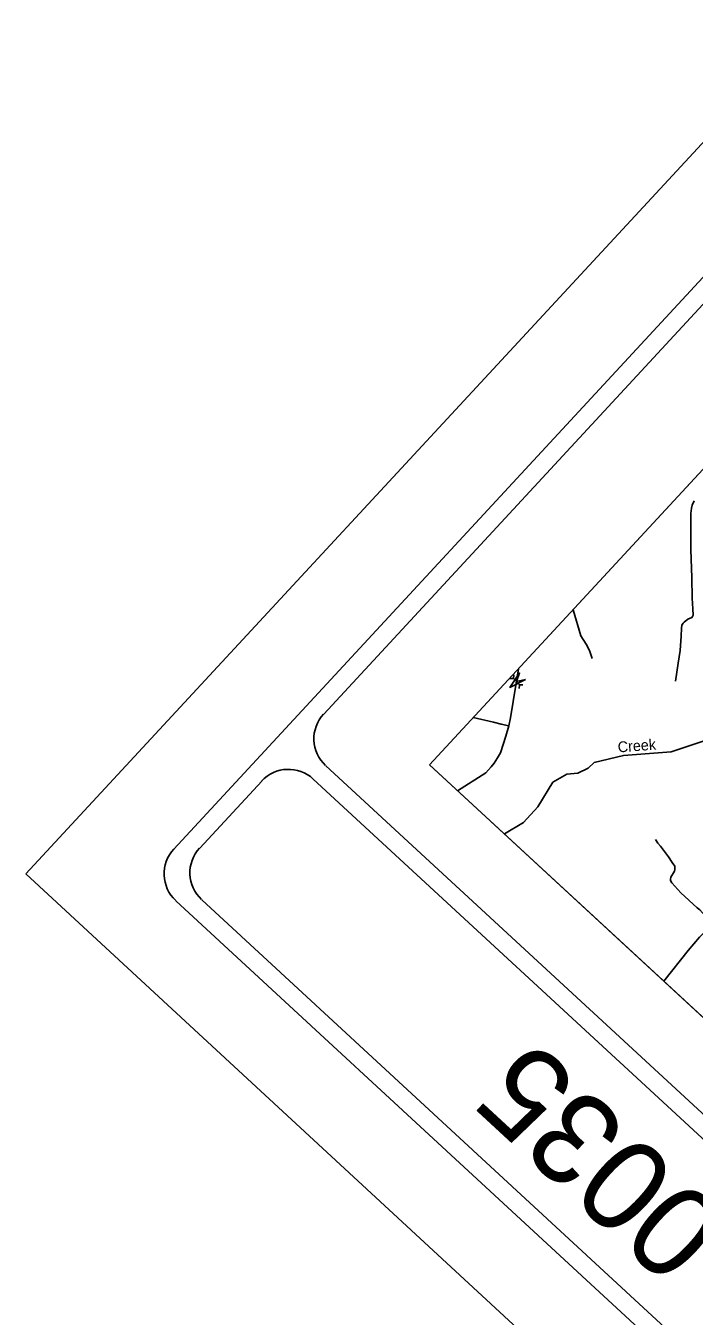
# Model space of a CAD drawing. Extents: x 1766669 to 1770980, y 998119 to 1002502.
# Drawn here: x 1766669 to 1767071, y 999494 to 1000271 of the extents above; entities that cross this region are included whole.
import ezdxf

# ---------------------------------------------------------------- set-up
doc = ezdxf.new("R2010")
doc.units = 0
for name, color, linetype in [('Default', 7, 'Continuous'), ('Default Symbol CELL', 7, 'Continuous'), ('Exist DTM Breakline', 7, 'Continuous'), ('Exist DTM Regular Point CELL', 7, 'Continuous'), ('Exist Property Iron Pin CELL', 7, 'Continuous'), ('Exist Roads EOP', 7, 'Continuous'), ('Exist Utilities Sanitary Sewer Manhole CELL', 7, 'Continuous'), ('PH Exist DTM Breakline', 7, 'Continuous')]:
    doc.layers.add(name, color=color, linetype=linetype)

msp = doc.modelspace()

# ---------------------------------------------------------------- linework, layer by layer
at = {"layer": 'Default'}
msp.add_lwpolyline([(1766911.45, 999825.82), (1767342.39, 1000292.03), (1767769.56, 999897.17), (1767338.62, 999430.96)], close=True, dxfattribs=at)
at = {"layer": 'Default Symbol CELL'}
for p, q in [((1769179.89, 1002395.47), (1766757.68, 999775.07)), ((1769180.49, 1002379.93), (1766847.82, 999856.35)), ((1766911.45, 999825.82), (1767342.36, 1000292.01)), ((1768196.36, 998579.87), (1766849, 999825.3)), ((1767395.61, 999378.28), (1766911.45, 999825.82)), ((1768487.42, 998295.86), (1766841.54, 999817.23))]:
    msp.add_line(p, q, dxfattribs=at)
for points in [[(1766810.51, 999815.99), (1766773.2, 999775.67)], [(1766758.86, 999744.06), (1768420.84, 998207.8)], [(1766758.9, 999744.01), (1768420.91, 998207.73)], [(1766758.9, 999744.01), (1768420.91, 998207.73)], [(1766774.44, 999744.64), (1768420.3, 998223.25)]]:
    msp.add_lwpolyline(points, dxfattribs=at)
for centre, start, end in [((1766863.85, 999841.51), 137.25123, 227.25123), ((1766826.56, 999801.17), 47.25123, 137.25123), ((1766773.75, 999760.22), 137.25123, 227.25123), ((1766789.27, 999760.83), 137.25123, 227.25123)]:
    msp.add_arc(centre, 21.97, start, end, dxfattribs=at)
at = {"layer": 'Exist DTM Breakline'}
for points in [[(1767070.65, 999984.82), (1767069.43, 999982.14), (1767068.93, 999980.26), (1767068.79, 999978.76), (1767068.6, 999977.2), (1767068.66, 999974.35), (1767068.56, 999955.32), (1767069.17, 999938.56), (1767069.46, 999926.07), (1767069.71, 999919.74), (1767069.92, 999915.92), (1767069.69, 999915.14), (1767069.2, 999914.6), (1767066.82, 999913.41), (1767064.52, 999911.65), (1767063.92, 999911.07), (1767063.16, 999909.84), (1767062.99, 999908), (1767062.74, 999903.2), (1767062.23, 999894.73), (1767060.94, 999887.07), (1767059.34, 999876.27)], [(1766997.75, 999919.19), (1767002.5, 999903.56), (1767005.58, 999898.48), (1767007.55, 999894.57), (1767008.93, 999891.11), (1767009.28, 999889.82)], [(1766964.91, 999883.66), (1766960.05, 999854.11), (1766959.15, 999849.29)], [(1766937.76, 999854.29), (1766949.98, 999851.43), (1766954.45, 999850.35), (1766959.15, 999849.29)], [(1766959.15, 999849.29), (1766957.36, 999843.01), (1766954.14, 999833.09), (1766952.39, 999829.95), (1766950.26, 999826.85), (1766948.6, 999824.63), (1766945.31, 999821.04), (1766928.27, 999810.27)], [(1767081.5, 999729.23), (1767078.42, 999733.41), (1767077.12, 999734.95), (1767074.1, 999738.51), (1767072.32, 999739.83), (1767062.55, 999748.8), (1767058.99, 999752.71), (1767057.13, 999754.84), (1767056.29, 999756.3), (1767056.33, 999757.04), (1767056.65, 999758.12), (1767058.82, 999761.77), (1767059.06, 999762.9), (1767059.05, 999763.97), (1767058.97, 999764.77), (1767057.44, 999767.04), (1767055.19, 999770.52), (1767050.27, 999776.85), (1767048.82, 999778.68), (1767047.32, 999780.81)], [(1767052.3, 999695.62), (1767067.05, 999714.05), (1767073.82, 999722.16), (1767077.44, 999725.69), (1767081.5, 999729.23)]]:
    msp.add_lwpolyline(points, dxfattribs=at)
at = {"layer": 'Exist Property Iron Pin CELL'}
for p, q in [((1766959.81, 999877.89), (1766961.99, 999877.83)), ((1766962.17, 999880), (1766961.99, 999877.83)), ((1766961.99, 999877.83), (1766965.46, 999873.95)), ((1766965.28, 999871.78), (1766965.46, 999873.95)), ((1766967.64, 999873.89), (1766965.46, 999873.95))]:
    msp.add_line(p, q, dxfattribs=at)
at = {"layer": 'Exist Roads EOP'}
for points in [[(1767127.45, 999852.04), (1767117.35, 999852.94), (1767104.67, 999845.68), (1767096.41, 999842.6), (1767081.44, 999841.91), (1767056.77, 999833.6), (1767028.19, 999831.39), (1767010.54, 999827.31)], [(1767010.54, 999827.31), (1767006.87, 999823.92), (1767000.63, 999820.89), (1766994.05, 999820.17), (1766985.64, 999815.3), (1766976.6, 999800.63), (1766967.86, 999791.14), (1766956.43, 999784.24)]]:
    msp.add_lwpolyline(points, dxfattribs=at)
at = {"layer": 'Exist Utilities Sanitary Sewer Manhole CELL'}
msp.add_lwpolyline([(1766969.17, 999877.14), (1766959.82, 999872.38), (1766965.55, 999881.18), (1766963.72, 999875.89)], close=True, dxfattribs=at)
at = {"layer": 'PH Exist DTM Breakline'}
msp.add_lwpolyline([(1766668.62, 999760.16), (1769205.64, 1002501.94), (1770979.75, 1000860.32), (1768442.74, 998118.54)], close=True, dxfattribs=at)

# ---------------------------------------------------------------- texts
at = {"layer": 'Default Symbol CELL'}
msp.add_text('TIP PROJECT: HB-0035', height=54.9341, rotation=137.25123, dxfattribs=at).set_placement((1767566.03, 999113.48))
at = {"layer": 'Exist DTM Regular Point CELL'}
msp.add_text('Creek', height=6.452, rotation=4.4203, dxfattribs=at).set_placement((1767024.87, 999833.26))

doc.saveas('drawing.dxf')
